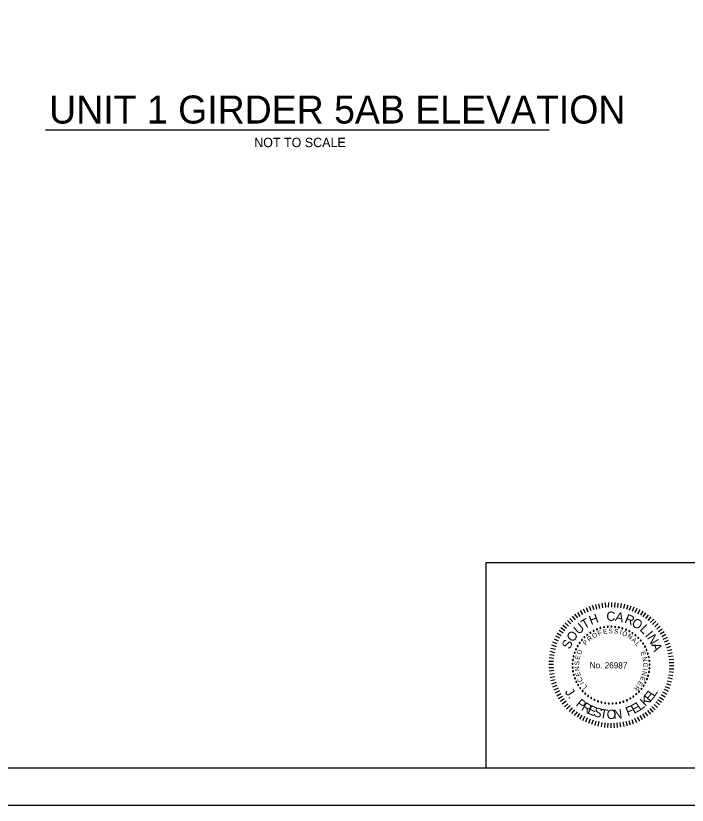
# Model space of a CAD drawing. Extents: x -383 to 14, y -392 to -94.
# Drawn here: x -239.84 to -203.87, y -187.49 to -145.21 of the extents above; entities that cross this region are included whole.
import ezdxf

# ---------------------------------------------------------------- set-up
doc = ezdxf.new("R2010")
doc.units = 0
for name, color, linetype in [('BR_BORDER LINES', 7, 'Continuous'), ('BR_TEXT', 7, 'Continuous'), ('Level 31', 7, 'Continuous')]:
    doc.layers.add(name, color=color, linetype=linetype)

msp = doc.modelspace()

# ---------------------------------------------------------------- linework, layer by layer
at = {"layer": 'BR_BORDER LINES'}
for p, q in [((-214.64, -174.489), (-193.18, -174.489)), ((-214.64, -185.489), (-214.64, -174.489)), ((-297.843, -185.489), (-163.178, -185.489))]:
    msp.add_line(p, q, dxfattribs=at)
at = {"layer": 'BR_TEXT'}
for p, q in [((-238.25, -151.32), (-211.269, -151.32)), ((-208.552, -176.946), (-208.608, -176.709)), ((-208.394, -176.917), (-208.429, -176.673)), ((-208.236, -176.901), (-208.251, -176.657)), ((-208.077, -176.892), (-208.075, -176.634)), ((-207.909, -176.883), (-207.907, -176.636)), ((-207.741, -176.895), (-207.732, -176.637)), ((-207.58, -176.906), (-207.561, -176.663)), ((-207.426, -176.925), (-207.382, -176.681)), ((-209.461, -177.282), (-209.582, -177.065)), ((-209.323, -177.211), (-209.427, -176.987)), ((-209.175, -177.144), (-209.269, -176.92)), ((-209.02, -177.076), (-209.103, -176.842)), ((-208.861, -177.026), (-208.949, -176.795)), ((-208.717, -176.986), (-208.77, -176.742)), ((-207.265, -176.957), (-207.208, -176.721)), ((-207.1, -176.999), (-207.036, -176.756)), ((-206.953, -177.042), (-206.865, -176.813)), ((-206.795, -177.095), (-206.708, -176.862)), ((-206.652, -177.165), (-206.54, -176.942)), ((-206.508, -177.234), (-206.383, -177.012)), ((-206.358, -177.308), (-206.229, -177.093)), ((-209.993, -177.662), (-210.159, -177.482)), ((-209.861, -177.564), (-210.021, -177.363)), ((-209.726, -177.462), (-209.883, -177.258)), ((-209.602, -177.377), (-209.724, -177.16)), ((-206.225, -177.405), (-206.089, -177.19)), ((-206.091, -177.492), (-205.946, -177.291)), ((-205.962, -177.596), (-205.799, -177.398)), ((-205.836, -177.696), (-205.663, -177.519)), ((-210.328, -178.02), (-210.526, -177.864)), ((-210.228, -177.894), (-210.402, -177.724)), ((-210.11, -177.771), (-210.287, -177.594)), ((-205.723, -177.807), (-205.55, -177.634)), ((-205.611, -177.932), (-205.421, -177.765)), ((-205.502, -178.06), (-205.316, -177.907)), ((-210.617, -178.416), (-210.832, -178.287)), ((-210.519, -178.269), (-210.735, -178.137)), ((-210.432, -178.153), (-210.63, -177.993)), ((-205.407, -178.194), (-205.21, -178.038)), ((-205.319, -178.312), (-205.109, -178.183)), ((-205.231, -178.46), (-205.017, -178.335)), ((-210.826, -178.853), (-211.059, -178.766)), ((-210.756, -178.699), (-210.985, -178.598)), ((-210.686, -178.552), (-210.912, -178.441)), ((-205.16, -178.598), (-204.929, -178.49)), ((-205.089, -178.746), (-204.862, -178.648)), ((-205.022, -178.901), (-204.795, -178.817)), ((-210.925, -179.158), (-211.168, -179.098)), ((-210.876, -179.014), (-211.122, -178.923)), ((-204.968, -179.063), (-204.738, -178.976)), ((-204.928, -179.207), (-204.688, -179.151)), ((-211.015, -179.634), (-211.261, -179.605)), ((-210.996, -179.47), (-211.24, -179.437)), ((-210.954, -179.326), (-211.204, -179.262)), ((-204.895, -179.376), (-204.654, -179.316)), ((-204.862, -179.52), (-204.625, -179.491)), ((-204.836, -179.685), (-204.592, -179.66)), ((-211.034, -179.957), (-211.285, -179.955)), ((-211.026, -179.792), (-211.284, -179.79)), ((-204.831, -179.843), (-204.59, -179.845)), ((-204.822, -180.008), (-204.578, -180.01)), ((-211.029, -180.129), (-211.286, -180.133)), ((-211.02, -180.283), (-211.267, -180.312)), ((-211.004, -180.448), (-211.248, -180.484)), ((-204.87, -180.499), (-204.634, -180.538)), ((-204.841, -180.334), (-204.598, -180.367)), ((-204.833, -180.18), (-204.593, -180.189)), ((-210.964, -180.606), (-211.215, -180.659)), ((-210.938, -180.775), (-211.182, -180.831)), ((-210.891, -180.923), (-211.139, -181.006)), ((-204.942, -180.824), (-204.702, -180.885)), ((-204.906, -180.656), (-204.666, -180.713)), ((-210.845, -181.077), (-211.079, -181.161)), ((-210.777, -181.226), (-211.008, -181.334)), ((-205.11, -181.272), (-204.884, -181.384)), ((-205.04, -181.125), (-204.814, -181.213)), ((-204.984, -180.971), (-204.755, -181.059)), ((-210.71, -181.37), (-210.937, -181.489)), ((-210.642, -181.519), (-210.859, -181.644)), ((-210.547, -181.667), (-210.765, -181.792)), ((-210.462, -181.784), (-210.663, -181.93)), ((-205.347, -181.71), (-205.139, -181.839)), ((-205.257, -181.563), (-205.045, -181.692)), ((-205.183, -181.416), (-204.954, -181.538)), ((-210.361, -181.919), (-210.561, -182.075)), ((-210.262, -182.054), (-210.439, -182.217)), ((-210.146, -182.158), (-210.326, -182.338)), ((-205.76, -182.194), (-205.589, -182.377)), ((-205.645, -182.092), (-205.458, -182.258)), ((-205.535, -181.959), (-205.351, -182.118)), ((-205.437, -181.826), (-205.243, -181.975)), ((-210.031, -182.279), (-210.2, -182.463)), ((-209.901, -182.383), (-210.064, -182.57)), ((-209.768, -182.487), (-209.928, -182.678)), ((-209.645, -182.574), (-209.77, -182.782)), ((-206.268, -182.602), (-206.135, -182.812)), ((-206.133, -182.517), (-205.99, -182.71)), ((-206.002, -182.415), (-205.842, -182.605)), ((-205.874, -182.313), (-205.704, -182.5)), ((-209.505, -182.664), (-209.63, -182.879)), ((-209.368, -182.744), (-209.477, -182.967)), ((-209.221, -182.814), (-209.319, -183.037)), ((-209.068, -182.884), (-209.155, -183.11)), ((-208.91, -182.933), (-209.001, -183.166)), ((-208.766, -182.983), (-208.823, -183.219)), ((-208.602, -183.011), (-208.662, -183.258)), ((-207.315, -183.022), (-207.262, -183.27)), ((-207.15, -182.996), (-207.09, -183.233)), ((-207.002, -182.949), (-206.918, -183.183)), ((-206.843, -182.902), (-206.759, -183.13)), ((-206.699, -182.835), (-206.591, -183.059)), ((-206.554, -182.768), (-206.432, -182.992)), ((-206.402, -182.69), (-206.277, -182.907)), ((-208.444, -183.057), (-208.484, -183.29)), ((-208.287, -183.076), (-208.306, -183.323)), ((-208.129, -183.087), (-208.131, -183.335)), ((-207.961, -183.099), (-207.963, -183.343)), ((-207.792, -183.09), (-207.787, -183.338)), ((-207.631, -183.081), (-207.616, -183.329)), ((-207.476, -183.065), (-207.437, -183.299))]:
    msp.add_line(p, q, dxfattribs=at)
for centre, start, end in [((-208.517, -178.003), 16.1422, 196.1422), ((-208.323, -177.957), 10.6038, 190.6038), ((-208.323, -177.957), 190.6038, 10.6038), ((-208.126, -177.93), 5.0653, 185.0653), ((-208.126, -177.93), 185.0653, 5.0653), ((-207.926, -177.923), 359.5268, 179.5268), ((-207.926, -177.923), 179.5268, 359.5268), ((-207.727, -177.934), 173.9884, 353.9884), ((-207.727, -177.934), 353.9884, 173.9884), ((-207.531, -177.965), 168.4499, 348.4499), ((-207.531, -177.965), 348.4499, 168.4499), ((-209.223, -178.364), 38.2961, 218.2961), ((-209.223, -178.364), 218.2961, 38.2961), ((-209.06, -178.248), 32.7576, 212.7576), ((-209.06, -178.248), 212.7576, 32.7576), ((-208.887, -178.149), 27.2191, 207.2191), ((-208.887, -178.149), 207.2191, 27.2191), ((-208.706, -178.067), 21.6807, 201.6807), ((-208.706, -178.067), 201.6807, 21.6807), ((-208.517, -178.003), 196.1422, 16.1422), ((-207.338, -178.015), 162.9114, 342.9114), ((-207.338, -178.015), 342.9114, 162.9114), ((-207.15, -178.083), 157.373, 337.373), ((-207.15, -178.083), 337.373, 157.373), ((-206.97, -178.169), 151.8345, 331.8345), ((-206.97, -178.169), 331.8345, 151.8345), ((-206.8, -178.272), 146.2961, 326.2961), ((-206.8, -178.272), 326.2961, 146.2961), ((-206.639, -178.39), 140.7576, 320.7576), ((-206.639, -178.39), 320.7576, 140.7576), ((-209.633, -178.796), 54.9114, 234.9114), ((-209.633, -178.796), 234.9114, 54.9114), ((-209.511, -178.639), 49.373, 229.373), ((-209.511, -178.639), 229.373, 49.373), ((-209.373, -178.495), 43.8345, 223.8345), ((-209.373, -178.495), 223.8345, 43.8345), ((-206.492, -178.524), 135.2191, 315.2191), ((-206.492, -178.524), 315.2191, 135.2191), ((-206.357, -178.671), 129.6807, 309.6807), ((-206.357, -178.671), 309.6807, 129.6807), ((-206.238, -178.831), 124.1422, 304.1422), ((-206.238, -178.831), 304.1422, 124.1422), ((-209.83, -179.142), 65.9884, 245.9884), ((-209.83, -179.142), 245.9884, 65.9884), ((-209.74, -178.964), 60.4499, 240.4499), ((-209.74, -178.964), 240.4499, 60.4499), ((-206.135, -179.001), 118.6038, 298.6038), ((-206.135, -179.001), 298.6038, 118.6038), ((-206.048, -179.181), 113.0653, 293.0653), ((-206.048, -179.181), 293.0653, 113.0653), ((-209.957, -179.52), 77.0653, 257.0653), ((-209.957, -179.52), 257.0653, 77.0653), ((-209.903, -179.328), 71.5268, 251.5268), ((-209.903, -179.328), 251.5268, 71.5268), ((-205.979, -179.368), 107.5268, 287.5268), ((-205.979, -179.368), 287.5268, 107.5268), ((-205.929, -179.561), 101.9884, 281.9884), ((-205.929, -179.561), 281.9884, 101.9884), ((-210.009, -179.914), 88.1422, 268.1422), ((-210.006, -180.114), 93.6807, 273.6807), ((-209.993, -179.716), 82.6038, 262.6038), ((-210.009, -179.914), 268.1422, 88.1422), ((-210.006, -180.114), 273.6807, 93.6807), ((-209.993, -179.716), 262.6038, 82.6038), ((-205.897, -179.758), 96.4499, 276.4499), ((-205.885, -179.957), 90.9114, 270.9114), ((-205.897, -179.758), 276.4499, 96.4499), ((-205.885, -179.957), 270.9114, 90.9114), ((-209.984, -180.312), 99.2191, 279.2191), ((-209.984, -180.312), 279.2191, 99.2191), ((-209.943, -180.507), 104.7576, 284.7576), ((-209.943, -180.507), 284.7576, 104.7576), ((-205.963, -180.548), 74.2961, 254.2961), ((-205.918, -180.353), 79.8345, 259.8345), ((-205.918, -180.353), 259.8345, 79.8345), ((-205.892, -180.156), 85.373, 265.373), ((-205.892, -180.156), 265.373, 85.373), ((-209.884, -180.697), 110.2961, 290.2961), ((-209.884, -180.697), 290.2961, 110.2961), ((-209.806, -180.881), 115.8345, 295.8345), ((-209.806, -180.881), 295.8345, 115.8345), ((-206.108, -180.918), 63.2191, 243.2191), ((-206.108, -180.918), 243.2191, 63.2191), ((-206.026, -180.737), 68.7576, 248.7576), ((-206.026, -180.737), 248.7576, 68.7576), ((-205.963, -180.548), 254.2961, 74.2961), ((-209.711, -181.056), 121.373, 301.373), ((-209.711, -181.056), 301.373, 121.373), ((-209.599, -181.221), 126.9114, 306.9114), ((-209.599, -181.221), 306.9114, 126.9114), ((-209.472, -181.375), 132.4499, 312.4499), ((-209.472, -181.375), 312.4499, 132.4499), ((-206.321, -181.255), 52.1422, 232.1422), ((-206.321, -181.255), 232.1422, 52.1422), ((-206.207, -181.092), 57.6807, 237.6807), ((-206.207, -181.092), 237.6807, 57.6807), ((-209.331, -181.515), 137.9884, 317.9884), ((-209.331, -181.515), 317.9884, 137.9884), ((-209.177, -181.642), 143.5268, 323.5268), ((-209.177, -181.642), 323.5268, 143.5268), ((-209.011, -181.753), 149.0653, 329.0653), ((-209.011, -181.753), 329.0653, 149.0653), ((-206.92, -181.774), 29.9884, 209.9884), ((-206.92, -181.774), 209.9884, 29.9884), ((-206.752, -181.667), 35.5268, 215.5268), ((-206.752, -181.667), 215.5268, 35.5268), ((-206.596, -181.543), 41.0653, 221.0653), ((-206.596, -181.543), 221.0653, 41.0653), ((-206.452, -181.406), 46.6038, 226.6038), ((-206.452, -181.406), 226.6038, 46.6038), ((-208.836, -181.847), 154.6038, 334.6038), ((-208.836, -181.847), 334.6038, 154.6038), ((-208.652, -181.924), 160.1422, 340.1422), ((-208.652, -181.924), 340.1422, 160.1422), ((-208.462, -181.983), 165.6807, 345.6807), ((-208.462, -181.983), 345.6807, 165.6807), ((-208.267, -182.023), 171.2191, 351.2191), ((-208.267, -182.023), 351.2191, 171.2191), ((-208.068, -182.045), 356.7576, 176.7576), ((-208.068, -182.045), 176.7576, 356.7576), ((-207.869, -182.047), 2.2961, 182.2961), ((-207.869, -182.047), 182.2961, 2.2961), ((-207.67, -182.029), 7.8345, 187.8345), ((-207.67, -182.029), 187.8345, 7.8345), ((-207.474, -181.993), 13.373, 193.373), ((-207.474, -181.993), 193.373, 13.373), ((-207.283, -181.938), 18.9114, 198.9114), ((-207.283, -181.938), 198.9114, 18.9114), ((-207.098, -181.865), 24.4499, 204.4499), ((-207.098, -181.865), 204.4499, 24.4499)]:
    msp.add_arc(centre, 0.028, start, end, dxfattribs=at)
at = {"layer": 'Level 31'}
msp.add_lwpolyline([(-305.176, -187.489), (-161.176, -187.489), (-161.176, -99.489), (-305.176, -99.489)], close=True, dxfattribs=at)

# ---------------------------------------------------------------- texts
at = {"layer": 'BR_TEXT'}
for s, height, p in [('UNIT 1 GIRDER 5AB ELEVATION', 1.5, (-238.053, -150.983)), ('NOT TO SCALE', 0.5, (-227.066, -152.247))]:
    msp.add_text(s, height=height, dxfattribs=at).set_placement(p)
for s, height, rotation, p in [('C', 0.496, 359.5482, (-208.2, -177.612)), ('T', 0.496, 30.4992, (-209.37, -178.076)), ('H', 0.496, 20.3637, (-209.018, -177.846)), ('A', 0.496, 348.1981, (-207.755, -177.609)), ('R', 0.496, 337.4344, (-207.262, -177.689)), ('O', 0.496, 326.5869, (-206.893, -177.836)), ('U', 0.496, 40.8022, (-209.694, -178.375)), ('L', 0.496, 315.9488, (-206.442, -178.107)), ('O', 0.496, 52.0267, (-209.993, -178.79)), ('O', 0.249, 30.8477, (-208.882, -178.561)), ('F', 0.249, 20.6127, (-208.613, -178.417)), ('E', 0.249, 11.4103, (-208.352, -178.33)), ('S', 0.249, 2.208, (-208.081, -178.286)), ('S', 0.249, 352.6608, (-207.796, -178.287)), ('I', 0.249, 343.1136, (-207.515, -178.335)), ('O', 0.249, 338.4392, (-207.381, -178.376)), ('N', 0.249, 328.2042, (-207.103, -178.501)), ('I', 0.496, 308.6613, (-206.157, -178.404)), ('N', 0.496, 300.7037, (-206.035, -178.521)), ('S', 0.496, 63.2511, (-210.174, -179.173)), ('P', 0.249, 49.9421, (-209.299, -178.947)), ('R', 0.249, 40.3949, (-209.107, -178.737)), ('A', 0.249, 318.657, (-206.867, -178.662)), ('L', 0.249, 309.4546, (-206.668, -178.851)), ('D', 0.249, 69.0364, (-209.567, -179.448)), ('E', 0.249, 291.049, (-206.372, -179.312)), ('A', 0.496, 289.4792, (-205.798, -178.894)), ('E', 0.249, 78.2388, (-209.633, -179.715)), ('N', 0.249, 281.8466, (-206.283, -179.572)), ('S', 0.249, 87.786, (-209.656, -179.999)), ('N', 0.249, 97.3332, (-209.632, -180.283)), ('No. 26987', 0.327, 359.5268, (-209.092, -180.153)), ('G', 0.249, 272.2995, (-206.237, -179.853)), ('E', 0.249, 106.5355, (-209.564, -180.549)), ('N', 0.249, 257.7339, (-206.256, -180.287)), ('I', 0.249, 262.4084, (-206.238, -180.149)), ('C', 0.249, 116.4266, (-209.444, -180.819)), ('I', 0.249, 121.1011, (-209.372, -180.939)), ('E', 0.249, 238.9844, (-206.44, -180.814)), ('E', 0.249, 248.1867, (-206.328, -180.563)), ('J', 0.494, 302.9559, (-210.441, -181.421)), ('L', 0.249, 129.9595, (-209.209, -181.147)), ('R', 0.249, 229.782, (-206.591, -181.044)), ('E', 0.494, 49.3639, (-205.857, -181.989)), ('L', 0.494, 56.4247, (-205.627, -181.718)), ('.', 0.494, 309.3974, (-210.264, -181.693)), ('P', 0.494, 321.1035, (-209.871, -182.13)), ('K', 0.494, 42.3031, (-206.118, -182.229)), ('R', 0.494, 328.5359, (-209.578, -182.362)), ('E', 0.494, 335.9684, (-209.257, -182.555)), ('F', 0.494, 21.1206, (-207.05, -182.735)), ('E', 0.494, 28.1814, (-206.719, -182.605)), ('L', 0.494, 35.2422, (-206.407, -182.436)), ('S', 0.494, 343.0292, (-208.932, -182.698)), ('T', 0.494, 350.4617, (-208.573, -182.804)), ('O', 0.494, 358.1419, (-208.192, -182.863)), ('N', 0.494, 5.8221, (-207.805, -182.872))]:
    msp.add_text(s, height=height, rotation=rotation, dxfattribs=at).set_placement(p)

doc.saveas('drawing.dxf')
